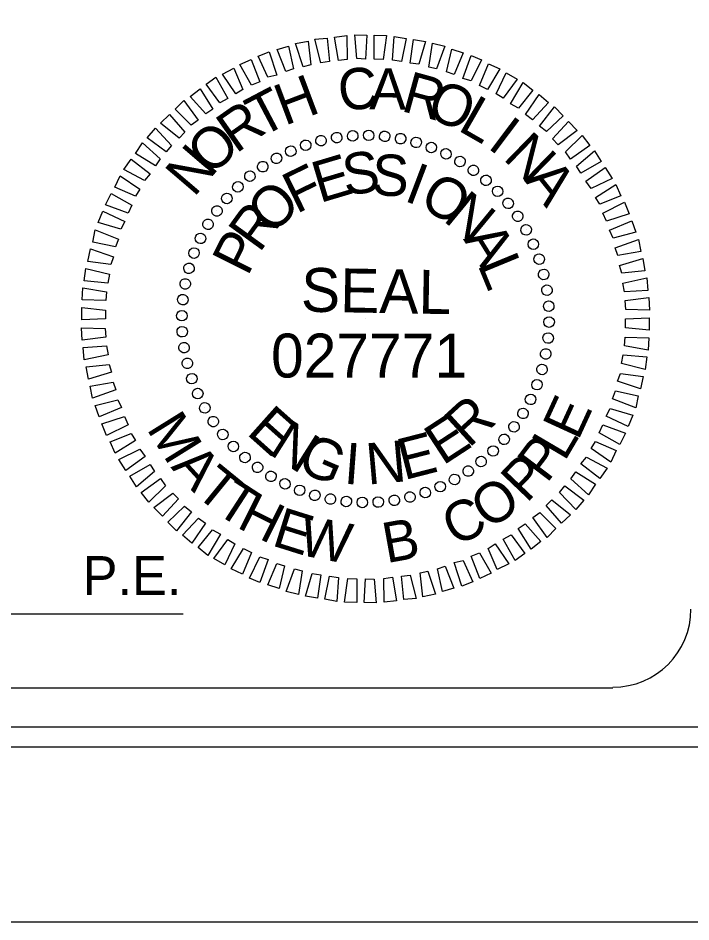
# Model space of a CAD drawing. Extents: x 2163579 to 2286010, y 210234 to 425257.
# Drawn here: x 2253219 to 2258732, y 331036 to 338445 of the extents above; entities that cross this region are included whole.
import ezdxf

# ---------------------------------------------------------------- set-up
doc = ezdxf.new("R2010")
doc.units = 0
for name, color, linetype in [('Sheet Cutting Line CELL', 7, 'Continuous'), ('Sheet Plot Border Inside CELL', 7, 'Continuous'), ('Sheet Plot Border Outside CELL', 7, 'Continuous'), ('Sheet Professional Seal CELL', 7, 'Continuous'), ('Sheet Title CELL', 7, 'Continuous')]:
    doc.layers.add(name, color=color, linetype=linetype)

msp = doc.modelspace()

# ---------------------------------------------------------------- linework, layer by layer
at = {"layer": 'Sheet Cutting Line CELL'}
msp.add_line((2163579, 331036.3), (2271355, 331036.3), dxfattribs=at)
at = {"layer": 'Sheet Plot Border Inside CELL'}
msp.add_lwpolyline([(2164411, 332472.3), (2271067, 332472.3), (2271067, 399998.7), (2164411, 399998.7)], close=True, dxfattribs=at)
at = {"layer": 'Sheet Plot Border Outside CELL'}
msp.add_lwpolyline([(2271355, 401435.5), (2163579, 401435.5), (2163579, 331036.3), (2271355, 331036.3)], close=True, dxfattribs=at)
at = {"layer": 'Sheet Professional Seal CELL'}
for p, q in [((2255832, 337464), (2255832, 337464)), ((2255961, 337482), (2255961, 337482)), ((2256093, 337485), (2256093, 337485)), ((2256225, 337476), (2256225, 337476)), ((2256354, 337455), (2256354, 337455)), ((2255574, 337404), (2255574, 337404)), ((2255700, 337440), (2255700, 337440)), ((2256480, 337428), (2256480, 337428)), ((2256606, 337386), (2256606, 337386)), ((2255454, 337356), (2255454, 337356)), ((2256726, 337332), (2256726, 337332)), ((2255337, 337296), (2255337, 337296)), ((2256843, 337272), (2256843, 337272)), ((2255223, 337227), (2255223, 337227)), ((2256951, 337197), (2256951, 337197)), ((2255118, 337152), (2255118, 337152)), ((2257056, 337116), (2257056, 337116)), ((2255019, 337062), (2255019, 337062)), ((2257149, 337026), (2257149, 337026)), ((2254929, 336969), (2254929, 336969)), ((2254848, 336864), (2254848, 336864)), ((2257239, 336927), (2257239, 336927)), ((2257314, 336822), (2257314, 336822)), ((2254773, 336756), (2254773, 336756)), ((2254713, 336639), (2254713, 336639)), ((2257383, 336708), (2257383, 336708)), ((2257443, 336591), (2257443, 336591)), ((2254659, 336519), (2254659, 336519)), ((2257491, 336471), (2257491, 336471)), ((2254617, 336393), (2254617, 336393)), ((2257527, 336345), (2257527, 336345)), ((2254590, 336267), (2254590, 336267)), ((2257551, 336213), (2257551, 336213)), ((2254569, 336138), (2254569, 336138)), ((2257569, 336084), (2257569, 336084)), ((2254560, 336006), (2254560, 336006)), ((2256066, 335979), (2256066, 335979)), ((2257572, 335952), (2257572, 335952)), ((2254563, 335874), (2254563, 335874)), ((2257563, 335820), (2257563, 335820)), ((2254581, 335745), (2254581, 335745)), ((2257542, 335691), (2257542, 335691)), ((2254605, 335613), (2254605, 335613)), ((2257515, 335565), (2257515, 335565)), ((2254641, 335487), (2254641, 335487)), ((2257473, 335439), (2257473, 335439)), ((2254689, 335367), (2254689, 335367)), ((2257419, 335319), (2257419, 335319)), ((2254749, 335250), (2254749, 335250)), ((2257359, 335202), (2257359, 335202)), ((2254818, 335136), (2254818, 335136)), ((2257284, 335094), (2257284, 335094)), ((2254893, 335031), (2254893, 335031)), ((2257203, 334989), (2257203, 334989)), ((2254983, 334932), (2254983, 334932)), ((2257113, 334896), (2257113, 334896)), ((2255076, 334842), (2255076, 334842)), ((2257014, 334806), (2257014, 334806)), ((2255181, 334761), (2255181, 334761)), ((2256909, 334731), (2256909, 334731)), ((2255289, 334686), (2255289, 334686)), ((2256795, 334662), (2256795, 334662)), ((2255406, 334626), (2255406, 334626)), ((2255526, 334572), (2255526, 334572)), ((2256678, 334602), (2256678, 334602)), ((2255652, 334530), (2255652, 334530)), ((2255778, 334503), (2255778, 334503)), ((2256300, 334494), (2256300, 334494)), ((2256432, 334518), (2256432, 334518)), ((2256558, 334554), (2256558, 334554)), ((2255907, 334482), (2255907, 334482)), ((2256039, 334473), (2256039, 334473)), ((2256171, 334476), (2256171, 334476))]:
    msp.add_line(p, q, dxfattribs=at)
for points in [[(2255700, 338079), (2255652, 338271), (2255751, 338280), (2255772, 338088)], [(2255844, 338097), (2255811, 338289), (2255913, 338301), (2255916, 338106)], [(2255994, 338112), (2255979, 338307), (2256078, 338304), (2256066, 338109)], [(2256138, 338109), (2256138, 338304), (2256237, 338301), (2256210, 338106)], [(2256288, 338100), (2256300, 338295), (2256399, 338277), (2256360, 338088)], [(2256432, 338076), (2256459, 338268), (2256558, 338253), (2256504, 338067)], [(2255412, 338007), (2255343, 338187), (2255436, 338214), (2255475, 338028)], [(2255556, 338046), (2255493, 338235), (2255595, 338256), (2255619, 338061)], [(2256585, 338043), (2256615, 338238), (2256717, 338214), (2256648, 338028)], [(2255265, 337959), (2255187, 338133), (2255277, 338169), (2255340, 337977)], [(2256729, 338004), (2256774, 338190), (2256867, 338160), (2256792, 337983)], [(2256864, 337950), (2256933, 338139), (2257017, 338103), (2256933, 337929)], [(2255133, 337896), (2255037, 338064), (2255130, 338106), (2255199, 337923)], [(2256999, 337893), (2257074, 338070), (2257167, 338028), (2257065, 337860)], [(2255004, 337824), (2254893, 337986), (2254986, 338034), (2255061, 337860)], [(2257137, 337824), (2257218, 337995), (2257308, 337944), (2257194, 337788)], [(2254872, 337749), (2254761, 337902), (2254839, 337959), (2254938, 337785)], [(2257254, 337743), (2257359, 337917), (2257437, 337854), (2257320, 337707)], [(2254758, 337659), (2254629, 337803), (2254710, 337866), (2254815, 337698)], [(2254638, 337566), (2254506, 337698), (2254578, 337770), (2254695, 337608)], [(2257377, 337653), (2257488, 337818), (2257566, 337752), (2257434, 337611)], [(2257491, 337560), (2257614, 337716), (2257686, 337644), (2257548, 337515)], [(2254539, 337461), (2254386, 337584), (2254461, 337653), (2254587, 337509)], [(2254434, 337347), (2254278, 337464), (2254344, 337542), (2254476, 337401)], [(2257599, 337455), (2257728, 337596), (2257800, 337524), (2257644, 337407)], [(2257704, 337347), (2257842, 337482), (2257905, 337401), (2257746, 337287)], [(2254344, 337233), (2254182, 337335), (2254239, 337422), (2254383, 337290)], [(2257794, 337230), (2257941, 337356), (2257998, 337269), (2257830, 337173)], [(2254254, 337113), (2254086, 337203), (2254146, 337287), (2254302, 337167)], [(2257872, 337107), (2258031, 337221), (2258088, 337131), (2257914, 337047)], [(2254182, 336984), (2254011, 337059), (2254056, 337152), (2254218, 337041)], [(2254122, 336846), (2253936, 336915), (2253981, 337008), (2254152, 336912)], [(2257950, 336975), (2258118, 337080), (2258157, 336987), (2257986, 336918)], [(2258010, 336846), (2258187, 336936), (2258226, 336840), (2258040, 336780)], [(2254062, 336714), (2253876, 336768), (2253915, 336861), (2254095, 336777)], [(2258064, 336705), (2258247, 336783), (2258280, 336690), (2258094, 336642)], [(2254017, 336570), (2253831, 336609), (2253852, 336708), (2254041, 336633)], [(2258112, 336561), (2258304, 336630), (2258322, 336531), (2258133, 336498)], [(2253978, 336426), (2253792, 336450), (2253813, 336552), (2254002, 336489)], [(2258148, 336417), (2258337, 336474), (2258355, 336372), (2258166, 336354)], [(2253954, 336273), (2253762, 336291), (2253774, 336393), (2253969, 336345)], [(2258175, 336273), (2258370, 336315), (2258379, 336213), (2258187, 336201)], [(2253939, 336129), (2253744, 336135), (2253750, 336234), (2253945, 336201)], [(2258193, 336129), (2258388, 336153), (2258394, 336051), (2258199, 336057)], [(2253936, 335979), (2253741, 335970), (2253741, 336072), (2253936, 336051)], [(2258196, 335979), (2258391, 335988), (2258391, 335886), (2258196, 335907)], [(2253939, 335829), (2253744, 335805), (2253738, 335907), (2253933, 335901)], [(2258193, 335829), (2258388, 335823), (2258382, 335724), (2258187, 335757)], [(2253957, 335685), (2253762, 335643), (2253753, 335745), (2253945, 335757)], [(2258178, 335685), (2258370, 335667), (2258358, 335565), (2258163, 335613)], [(2253984, 335541), (2253795, 335484), (2253777, 335586), (2253966, 335604)], [(2258154, 335532), (2258340, 335508), (2258319, 335406), (2258130, 335469)], [(2254020, 335397), (2253828, 335328), (2253810, 335427), (2253999, 335460)], [(2258115, 335388), (2258301, 335349), (2258280, 335250), (2258091, 335325)], [(2254068, 335253), (2253885, 335175), (2253852, 335268), (2254038, 335316)], [(2258070, 335244), (2258256, 335190), (2258217, 335097), (2258037, 335181)], [(2254122, 335112), (2253945, 335022), (2253906, 335118), (2254092, 335178)], [(2258010, 335112), (2258196, 335043), (2258151, 334950), (2257980, 335046)], [(2254182, 334983), (2254014, 334878), (2253975, 334971), (2254146, 335040)], [(2257950, 334974), (2258121, 334899), (2258076, 334806), (2257914, 334917)], [(2254260, 334851), (2254101, 334737), (2254044, 334827), (2254218, 334911)], [(2254338, 334728), (2254191, 334602), (2254134, 334689), (2254302, 334785)], [(2257878, 334845), (2258046, 334755), (2257986, 334671), (2257830, 334791)], [(2257788, 334725), (2257950, 334623), (2257893, 334536), (2257749, 334668)], [(2254428, 334611), (2254290, 334476), (2254227, 334557), (2254386, 334671)], [(2257698, 334611), (2257854, 334494), (2257788, 334416), (2257656, 334557)], [(2254533, 334503), (2254404, 334362), (2254332, 334434), (2254488, 334551)], [(2257593, 334497), (2257746, 334374), (2257671, 334305), (2257545, 334449)], [(2254641, 334398), (2254518, 334242), (2254446, 334314), (2254584, 334443)], [(2254755, 334305), (2254644, 334140), (2254566, 334206), (2254698, 334347)], [(2257494, 334392), (2257626, 334260), (2257554, 334188), (2257437, 334350)], [(2257374, 334299), (2257503, 334155), (2257422, 334092), (2257317, 334260)], [(2254878, 334215), (2254773, 334041), (2254695, 334104), (2254812, 334251)], [(2257260, 334209), (2257371, 334056), (2257293, 333999), (2257194, 334173)], [(2254995, 334134), (2254914, 333963), (2254824, 334014), (2254938, 334170)], [(2257128, 334134), (2257239, 333972), (2257146, 333924), (2257071, 334098)], [(2255133, 334065), (2255058, 333888), (2254965, 333930), (2255067, 334098)], [(2256999, 334062), (2257095, 333894), (2257002, 333852), (2256933, 334035)], [(2255268, 334008), (2255199, 333819), (2255115, 333855), (2255199, 334029)], [(2255403, 333954), (2255358, 333768), (2255265, 333798), (2255340, 333975)], [(2256867, 333999), (2256945, 333825), (2256855, 333789), (2256792, 333981)], [(2255547, 333915), (2255517, 333720), (2255415, 333744), (2255484, 333930)], [(2256576, 333912), (2256639, 333723), (2256537, 333702), (2256513, 333897)], [(2256720, 333951), (2256789, 333771), (2256696, 333744), (2256657, 333930)], [(2255700, 333882), (2255673, 333690), (2255574, 333705), (2255628, 333891)], [(2255844, 333858), (2255832, 333663), (2255733, 333681), (2255772, 333870)], [(2255994, 333849), (2255994, 333654), (2255895, 333657), (2255922, 333852)], [(2256138, 333846), (2256153, 333651), (2256054, 333654), (2256066, 333849)], [(2256288, 333861), (2256321, 333669), (2256219, 333657), (2256216, 333852)], [(2256432, 333879), (2256480, 333687), (2256381, 333678), (2256360, 333870)]]:
    msp.add_lwpolyline(points, close=True, dxfattribs=at)
for centre, major_axis in [((2256092.2, 337483.6), (0.8, 43.2)), ((2255701.9, 337439.1), (-10.5, 41.9)), ((2255830.6, 337465.3), (-6.8, 42.7)), ((2255961, 337480.2), (-3, 43.1)), ((2256223.2, 337475.6), (4.5, 43)), ((2256353.1, 337456.2), (8.2, 42.4)), ((2256480.7, 337425.5), (11.9, 41.5)), ((2255453.9, 337353.7), (-17.6, 39.5)), ((2255576, 337401.8), (-14.1, 40.8)), ((2256605.2, 337383.9), (15.5, 40.3)), ((2256725.6, 337331.5), (18.9, 38.8)), ((2255336.4, 337295.2), (-20.9, 37.8)), ((2256841, 337268.9), (22.2, 37)), ((2255224.5, 337226.6), (-24.2, 35.8)), ((2256950.5, 337196.4), (25.4, 34.9)), ((2255119, 337148.5), (-27.2, 33.6)), ((2257053.2, 337114.7), (28.3, 32.6)), ((2255020.6, 337061.5), (-30, 31.1)), ((2254930.3, 336966.3), (-32.6, 28.3)), ((2257148.4, 337024.3), (31.1, 30)), ((2257235.4, 336926), (33.6, 27.2)), ((2254848.5, 336863.5), (-34.9, 25.4)), ((2257313.5, 336820.5), (35.8, 24.2)), ((2254776.1, 336754.1), (-37, 22.2)), ((2257382.1, 336708.6), (37.8, 20.9)), ((2254713.4, 336638.7), (-38.8, 18.9)), ((2257440.7, 336591.1), (39.5, 17.6)), ((2254661.1, 336518.3), (-40.3, 15.5)), ((2257488.8, 336468.9), (40.8, 14.1)), ((2254619.4, 336393.8), (-41.5, 11.9)), ((2257526.1, 336343.1), (41.9, 10.5)), ((2254588.8, 336266.2), (-42.4, 8.2)), ((2257552.2, 336214.4), (42.7, 6.8)), ((2254569.4, 336136.3), (-43, 4.5)), ((2257567.1, 336084), (43.1, 3)), ((2254561.4, 336005.3), (-43.2, 0.8)), ((2257570.5, 335952.8), (43.2, -0.8)), ((2254564.8, 335874.1), (-43.1, -3)), ((2257562.5, 335821.7), (43, -4.5)), ((2254579.7, 335743.6), (-42.7, -6.8)), ((2257543.1, 335691.9), (42.4, -8.2)), ((2254605.9, 335615), (-41.9, -10.5)), ((2257512.5, 335564.2), (41.5, -11.9)), ((2254643.1, 335489.1), (-40.8, -14.1)), ((2257470.8, 335439.8), (40.3, -15.5)), ((2254691.3, 335367), (-39.5, -17.6)), ((2257418.5, 335319.4), (38.8, -18.9)), ((2254749.8, 335249.5), (-37.8, -20.9)), ((2257355.8, 335204), (37, -22.2)), ((2254818.4, 335137.6), (-35.8, -24.2)), ((2254896.5, 335032), (-33.6, -27.2)), ((2257283.4, 335094.5), (34.9, -25.4)), ((2257201.6, 334991.8), (32.6, -28.3)), ((2254983.5, 334933.7), (-31.1, -30)), ((2257111.3, 334896.6), (30, -31.1)), ((2255078.7, 334843.3), (-28.3, -32.6)), ((2257013, 334809.6), (27.2, -33.6)), ((2255181.5, 334761.6), (-25.4, -34.9)), ((2255290.9, 334689.2), (-22.2, -37)), ((2256795.5, 334662.9), (20.9, -37.8)), ((2256907.4, 334731.5), (24.2, -35.8)), ((2255406.3, 334626.5), (-18.9, -38.8)), ((2256678, 334604.3), (17.6, -39.5)), ((2255526.7, 334574.2), (-15.5, -40.3)), ((2255651.2, 334532.5), (-11.9, -41.5)), ((2256430, 334518.9), (10.5, -41.9)), ((2256555.9, 334556.2), (14.1, -40.8)), ((2255778.8, 334501.9), (-8.2, -42.4)), ((2255908.7, 334482.5), (-4.5, -43)), ((2256039.7, 334474.5), (-0.8, -43.2)), ((2256170.9, 334477.9), (3, -43.1)), ((2256301.4, 334492.8), (6.8, -42.7))]:
    msp.add_ellipse(centre, major_axis=major_axis, ratio=0.999708, dxfattribs=at)
at = {"layer": 'Sheet Title CELL'}
msp.add_line((2245515, 333561.1), (2254571, 333560.3), dxfattribs=at)
for points in [[(2245307, 332956.3), (2258092.5, 332956.3)], [(2174907, 332635.5), (2269627, 332635.5)]]:
    msp.add_lwpolyline(points, dxfattribs=at)
msp.add_arc((2258092.5, 333599.9), 640, 270, 360, dxfattribs=at)

# ---------------------------------------------------------------- texts
at = {"layer": 'Sheet Professional Seal CELL'}
for s, height, rotation, p in [('C', 338.3, 6.21987, (2255859, 337680)), ('H', 338.3, 20.61948, (2255403, 337560)), ('A', 338.3, 359.02032, (2256096, 337698)), ('R', 338.3, 344.6211, (2256348, 337686)), ('O', 338.3, 337.42116, (2256549, 337641)), ('T', 338.3, 27.81977, (2255208, 337461)), ('L', 338.3, 330.22088, (2256813, 337530)), ('R', 338.3, 35.02051, (2255004, 337329)), ('I', 338.3, 323.02014, (2257056, 337386)), ('O', 338.3, 42.22174, (2254797, 337143)), ('N', 338.3, 315.81891, (2257185, 337293)), ('N', 338.3, 49.4235, (2254659, 336969)), ('E', 338.3, 16.61107, (2255691, 336927)), ('S', 338.3, 7.25561, (2255898, 336990)), ('S', 338.3, 357.9004, (2256114, 336993)), ('F', 338.3, 25.96703, (2255499, 336837)), ('I', 338.3, 339.1896, (2256372, 336951)), ('A', 338.3, 308.61715, (2257362, 337116)), ('O', 338.3, 44.68124, (2255301, 336660)), ('O', 338.3, 329.83348, (2256492, 336909)), ('N', 338.3, 320.47661, (2256693, 336789)), ('R', 338.3, 54.03965, (2255196, 336513)), ('P', 338.4, 63.39889, (2255100, 336321)), ('A', 338.3, 301.76027, (2256864, 336633)), ('L', 338.4, 292.40085, (2256981, 336426)), ('SEAL', 359.89, 359, (2255535, 336039)), ('R', 338.3, 42.48141, (2256912, 334914)), ('E', 330, 65.34584, (2257807.5, 334974.5)), ('E', 338.3, 318.27689, (2255082, 335040)), ('M', 330, 301.88628, (2254267.7, 335079.9)), ('E', 338.3, 33.12409, (2256699, 334773)), ('N', 338.3, 327.63396, (2255262, 334878)), ('G', 338.3, 336.99024, (2255490, 334743)), ('E', 338.3, 14.41176, (2256381, 334656)), ('P', 330, 52.95266, (2257551.3, 334624.1)), ('L', 330, 59.53564, (2257696.9, 334803.3)), ('I', 338.3, 355.7012, (2255883, 334629)), ('N', 338.3, 5.05639, (2256084, 334620)), ('A', 330, 312.56216, (2254465.4, 334762.4)), ('T', 330, 320.74796, (2254654.9, 334546.9)), ('P', 330, 46.36967, (2257386.2, 334462.8)), ('T', 330, 327.04472, (2254820.5, 334400.8)), ('O', 330, 35.66517, (2257081.6, 334243.9)), ('H', 330, 333.34149, (2255001.1, 334273.7)), ('C', 330, 26.79245, (2256801.8, 334108)), ('E', 330, 342.58629, (2255288.9, 334124.8)), ('W', 330, 349.16927, (2255506.6, 334047.9)), ('B', 330, 10.22051, (2256237.6, 333975.9))]:
    msp.add_text(s, height=height, rotation=rotation, dxfattribs=at).set_placement(p)
msp.add_text('027771', height=359.89, dxfattribs=at).set_placement((2255292, 335498.5))
at = {"layer": 'Sheet Title CELL'}
msp.add_text('P.E.', height=319.97, rotation=360, dxfattribs=at).set_placement((2253748.6, 333714.7))

doc.saveas('drawing.dxf')
